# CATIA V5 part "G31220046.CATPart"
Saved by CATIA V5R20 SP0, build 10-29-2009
Part number: G31220046
Revision: 8
Definition: design
Nomenclature: G31220046
Source: made
Description: NOT SPECIFIED
Bounding box of the stored display mesh (mm): x -8 to 46, y -15.5 to 15.5, z -15.5 to 15.5
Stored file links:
  C:\Users\Raffaele\Desktop\3D X SITO CF\BOLEX\23-BUSH REF 312\G31220046.CATPart

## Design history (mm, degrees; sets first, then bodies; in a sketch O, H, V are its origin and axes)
Body1 "MANIFOLD_SOLID_BREP #14707" (main body)
  Solid1: solid without history
Body2 "MANIFOLD_SOLID_BREP #14854"
  Solid2: solid without history
Body3 "MANIFOLD_SOLID_BREP #15001"
  Solid3: solid without history
Body4 "MANIFOLD_SOLID_BREP #15148"
  Solid4: solid without history
Body5 "MANIFOLD_SOLID_BREP #15295"
  Solid5: solid without history
Body6 "MANIFOLD_SOLID_BREP #15440"
  Solid6: solid without history
Body7 "MANIFOLD_SOLID_BREP #15585"
  Solid7: solid without history
Body8 "MANIFOLD_SOLID_BREP #15730"
  Solid8: solid without history
Body9 "MANIFOLD_SOLID_BREP #15875"
  Solid9: solid without history
Body10 "MANIFOLD_SOLID_BREP #16020"
  Solid10: solid without history
Body11 "MANIFOLD_SOLID_BREP #16165"
  Solid11: solid without history
Body12 "MANIFOLD_SOLID_BREP #16310"
  Solid12: solid without history
Body13 "MANIFOLD_SOLID_BREP #16455"
  Solid13: solid without history
Body14 "MANIFOLD_SOLID_BREP #16600"
  Solid14: solid without history
Body15 "MANIFOLD_SOLID_BREP #16745"
  Solid15: solid without history
Body16 "MANIFOLD_SOLID_BREP #16890"
  Solid16: solid without history
Body17 "MANIFOLD_SOLID_BREP #17035"
  Solid17: solid without history
Body18 "MANIFOLD_SOLID_BREP #17180"
  Solid18: solid without history
Body19 "MANIFOLD_SOLID_BREP #17325"
  Solid19: solid without history
Body20 "MANIFOLD_SOLID_BREP #17470"
  Solid20: solid without history
Body21 "MANIFOLD_SOLID_BREP #17615"
  Solid21: solid without history
Body22 "MANIFOLD_SOLID_BREP #17762"
  Solid22: solid without history
Body23 "MANIFOLD_SOLID_BREP #17907"
  Solid23: solid without history
Body24 "MANIFOLD_SOLID_BREP #18052"
  Solid24: solid without history
Body25 "MANIFOLD_SOLID_BREP #18199"
  Solid25: solid without history
Body26 "MANIFOLD_SOLID_BREP #18344"
  Solid26: solid without history
Body27 "MANIFOLD_SOLID_BREP #18489"
  Solid27: solid without history
Body28 "MANIFOLD_SOLID_BREP #18634"
  Solid28: solid without history
Body29 "MANIFOLD_SOLID_BREP #18779"
  Solid29: solid without history
Body30 "MANIFOLD_SOLID_BREP #18924"
  Solid30: solid without history
Body31 "MANIFOLD_SOLID_BREP #19069"
  Solid31: solid without history
Body32 "MANIFOLD_SOLID_BREP #19216"
  Solid32: solid without history
Body33 "MANIFOLD_SOLID_BREP #19363"
  Solid33: solid without history
Body34 "MANIFOLD_SOLID_BREP #19508"
  Solid34: solid without history
Body35 "MANIFOLD_SOLID_BREP #19653"
  Solid35: solid without history
Body36 "MANIFOLD_SOLID_BREP #19798"
  Solid36: solid without history
Body37 "MANIFOLD_SOLID_BREP #19943"
  Solid37: solid without history
Body38 "MANIFOLD_SOLID_BREP #20090"
  Solid38: solid without history
Body39 "MANIFOLD_SOLID_BREP #20235"
  Solid39: solid without history
Body40 "MANIFOLD_SOLID_BREP #20380"
  Solid40: solid without history
Body41 "MANIFOLD_SOLID_BREP #20527"
  Solid41: solid without history
Body42 "MANIFOLD_SOLID_BREP #20672"
  Solid42: solid without history
Body43 "MANIFOLD_SOLID_BREP #20817"
  Solid43: solid without history
Body44 "MANIFOLD_SOLID_BREP #20962"
  Solid44: solid without history
Body45 "MANIFOLD_SOLID_BREP #21107"
  Solid45: solid without history
Body46 "MANIFOLD_SOLID_BREP #21252"
  Solid46: solid without history
Body47 "MANIFOLD_SOLID_BREP #21397"
  Solid47: solid without history
Body48 "MANIFOLD_SOLID_BREP #21542"
  Solid48: solid without history
Body49 "MANIFOLD_SOLID_BREP #21687"
  Solid49: solid without history
Body50 "MANIFOLD_SOLID_BREP #21832"
  Solid50: solid without history
Body51 "MANIFOLD_SOLID_BREP #21977"
  Solid51: solid without history
Body52 "MANIFOLD_SOLID_BREP #22124"
  Solid52: solid without history
Body53 "MANIFOLD_SOLID_BREP #22269"
  Solid53: solid without history
Body54 "MANIFOLD_SOLID_BREP #22414"
  Solid54: solid without history
Body55 "MANIFOLD_SOLID_BREP #22561"
  Solid55: solid without history
Body56 "MANIFOLD_SOLID_BREP #22708"
  Solid56: solid without history
Body57 "MANIFOLD_SOLID_BREP #22855"
  Solid57: solid without history
Body58 "MANIFOLD_SOLID_BREP #23000"
  Solid58: solid without history
Body59 "MANIFOLD_SOLID_BREP #23145"
  Solid59: solid without history
Body60 "MANIFOLD_SOLID_BREP #23290"
  Solid60: solid without history
Body61 "MANIFOLD_SOLID_BREP #23435"
  Solid61: solid without history
Body62 "MANIFOLD_SOLID_BREP #23580"
  Solid62: solid without history
Body63 "MANIFOLD_SOLID_BREP #23725"
  Solid63: solid without history
Body64 "MANIFOLD_SOLID_BREP #23872"
  Solid64: solid without history
Body65 "MANIFOLD_SOLID_BREP #24019"
  Solid65: solid without history
Body66 "MANIFOLD_SOLID_BREP #24164"
  Solid66: solid without history
Body67 "MANIFOLD_SOLID_BREP #24309"
  Solid67: solid without history
Body68 "MANIFOLD_SOLID_BREP #24454"
  Solid68: solid without history
Body69 "MANIFOLD_SOLID_BREP #24599"
  Solid69: solid without history
Body70 "MANIFOLD_SOLID_BREP #24746"
  Solid70: solid without history
Body71 "MANIFOLD_SOLID_BREP #24891"
  Solid71: solid without history
Body72 "MANIFOLD_SOLID_BREP #25036"
  Solid72: solid without history
Body73 "MANIFOLD_SOLID_BREP #25183"
  Solid73: solid without history
Body74 "MANIFOLD_SOLID_BREP #25328"
  Solid74: solid without history
Body75 "MANIFOLD_SOLID_BREP #25473"
  Solid75: solid without history
Body76 "MANIFOLD_SOLID_BREP #25618"
  Solid76: solid without history
Body77 "MANIFOLD_SOLID_BREP #25763"
  Solid77: solid without history
Body78 "MANIFOLD_SOLID_BREP #25908"
  Solid78: solid without history
Body79 "MANIFOLD_SOLID_BREP #26053"
  Solid79: solid without history
Body80 "MANIFOLD_SOLID_BREP #26198"
  Solid80: solid without history
Body81 "MANIFOLD_SOLID_BREP #26343"
  Solid81: solid without history
Body82 "MANIFOLD_SOLID_BREP #26488"
  Solid82: solid without history
Body83 "MANIFOLD_SOLID_BREP #26633"
  Solid83: solid without history
Body84 "MANIFOLD_SOLID_BREP #26778"
  Solid84: solid without history
Body85 "MANIFOLD_SOLID_BREP #26923"
  Solid85: solid without history
Body86 "MANIFOLD_SOLID_BREP #27070"
  Solid86: solid without history
Body87 "MANIFOLD_SOLID_BREP #27217"
  Solid87: solid without history
Body88 "MANIFOLD_SOLID_BREP #27364"
  Solid88: solid without history
Body89 "MANIFOLD_SOLID_BREP #27511"
  Solid89: solid without history
Body90 "MANIFOLD_SOLID_BREP #27656"
  Solid90: solid without history
Body91 "MANIFOLD_SOLID_BREP #27801"
  Solid91: solid without history
Body92 "MANIFOLD_SOLID_BREP #27946"
  Solid92: solid without history
Body93 "MANIFOLD_SOLID_BREP #28091"
  Solid93: solid without history
Body94 "MANIFOLD_SOLID_BREP #28236"
  Solid94: solid without history
Body95 "MANIFOLD_SOLID_BREP #28381"
  Solid95: solid without history
Body96 "MANIFOLD_SOLID_BREP #28526"
  Solid96: solid without history
Body97 "MANIFOLD_SOLID_BREP #28671"
  Solid97: solid without history
Body98 "MANIFOLD_SOLID_BREP #28818"
  Solid98: solid without history
Body99 "MANIFOLD_SOLID_BREP #28965"
  Solid99: solid without history
Body100 "MANIFOLD_SOLID_BREP #29110"
  Solid100: solid without history
Body101 "MANIFOLD_SOLID_BREP #29255"
  Solid101: solid without history
Body102 "MANIFOLD_SOLID_BREP #29400"
  Solid102: solid without history
Body103 "MANIFOLD_SOLID_BREP #29545"
  Solid103: solid without history
Body104 "MANIFOLD_SOLID_BREP #29692"
  Solid104: solid without history
Body105 "MANIFOLD_SOLID_BREP #29839"
  Solid105: solid without history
